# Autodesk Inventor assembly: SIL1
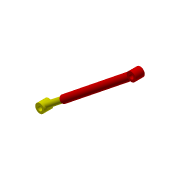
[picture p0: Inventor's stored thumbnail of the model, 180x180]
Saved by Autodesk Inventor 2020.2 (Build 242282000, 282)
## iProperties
Manager: www.cadconsulting.pl
Company: Fabian Stasiak CAD Consulting
Created: 2005-10
Part Number: SIL1
Document SubType Name: Assembly
Designer: F.Stasiak
Author: F.Stasiak
Subject: Zbiór ćwiczeń. Autodesk Inventor 2020. Kurs podstawowy
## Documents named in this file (3)
- C:\2020_Kurs_podstawowy\R6 Zespoły\Lustro\SIL1.iam
- C:\2020_Kurs_podstawowy\R6 Zespoły\Lustro\Cyl1.ipt
- C:\2020_Kurs_podstawowy\R6 Zespoły\Lustro\T1.ipt
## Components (2 placed, 2 different names)
1. Cyl1:1
2. T1:1
